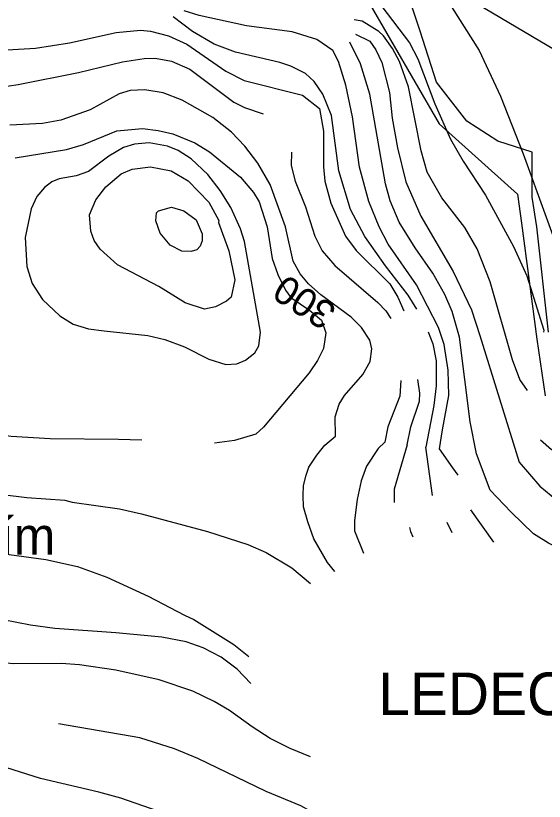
# Model space of a CAD drawing. Extents: x -662620 to -656370, y -1067090 to -1062990.
# Drawn here: x -660920.3 to -660671.9, y -1065837.4 to -1065468.5 of the extents above; entities that cross this region are included whole.
import ezdxf

# ---------------------------------------------------------------- set-up
doc = ezdxf.new("R2010")
doc.units = 0
for name, color, linetype in [('CHRANENE_LOZISKOVE_UZEMI', 7, 'Continuous'), ('HRANICE_KATASTRÁLNÍHO_ÚZEMÍ', 7, 'Continuous'), ('MÍSTNÍ_NÁZVY', 7, 'Continuous'), ('Ochr__pás__vod__zdroje_II__stupně', 7, 'Continuous'), ('POPIS_-_MZCHÚ', 7, 'Continuous'), ('VRSTEVNICE_ZDŮRAZNĚNÁ', 7, 'Continuous'), ('VRSTEVNICE_ZDŮRAZNĚNÁ_-_POPIS', 7, 'Continuous'), ('VRSTEVNICE_ZÁKLADNÍ', 7, 'Continuous')]:
    doc.layers.add(name, color=color, linetype=linetype)

msp = doc.modelspace()

# ---------------------------------------------------------------- linework, layer by layer
at = {"layer": 'CHRANENE_LOZISKOVE_UZEMI'}
msp.add_lwpolyline([(-661096.57, -1065944.42), (-661652.65, -1065558.91), (-661386.13, -1065362.86), (-661234.18, -1065237.85), (-660862.53, -1065376.49), (-660732.31, -1065445.66), (-660264.34, -1065722.38)], dxfattribs=at)
at = {"layer": 'HRANICE_KATASTRÁLNÍHO_ÚZEMÍ'}
msp.add_lwpolyline([(-660805.72, -1065089.02), (-660851.32, -1065259.88), (-660882.69, -1065372.12), (-660887.7, -1065375.53), (-660889.1, -1065376.51), (-660879.99, -1065382.24), (-660829.51, -1065412.73), (-660787.97, -1065437.5), (-660755.58, -1065459.98), (-660721.29, -1065519.33), (-660684.51, -1065552.34), (-660682.61, -1065565.91), (-660675.51, -1065620.4), (-660671.56, -1065647.03)], dxfattribs=at)
at = {"layer": 'Ochr__pás__vod__zdroje_II__stupně'}
msp.add_lwpolyline([(-660669.94, -1065617.13), (-660675.36, -1065567.65), (-660677.67, -1065553.71), (-660677.67, -1065532.65), (-660693.79, -1065527.44), (-660708.36, -1065518.08), (-660722.65, -1065499.69), (-660730.21, -1065475.73), (-660739.83, -1065447.13), (-660741.91, -1065434.08), (-660766.44, -1065423.12), (-660838.55, -1065385.6), (-660854.29, -1065377.16), (-660865.22, -1065371.3), (-660835.25, -1065270.78), (-660823.63, -1065223), (-660796.13, -1065127.73)], dxfattribs=at)
at = {"layer": 'VRSTEVNICE_ZDŮRAZNĚNÁ'}
for points in [[(-660870.75, -1065334.31), (-660842.73, -1065350.46), (-660822.72, -1065364.32), (-660778.7, -1065397.91), (-660748.54, -1065423.78), (-660735.1, -1065437.08), (-660721.52, -1065454.8), (-660702.51, -1065484.82), (-660692.51, -1065506.26), (-660681.93, -1065533.41), (-660660.21, -1065592.87), (-660641.91, -1065638.61), (-660634.76, -1065652.33), (-660626.19, -1065666.06), (-660609.48, -1065685.51)], [(-660721.19, -1065671.85), (-660719.77, -1065662.91), (-660716.81, -1065646.9), (-660717.09, -1065634.9), (-660718.95, -1065622.89), (-660721.67, -1065614.89), (-660731.96, -1065594.87), (-660745.25, -1065575.86), (-660749.54, -1065567.72), (-660754.4, -1065555.71), (-660758.69, -1065539.7), (-660761.97, -1065515.98), (-660765.12, -1065501.11), (-660768.55, -1065489.96), (-660771.27, -1065484.82), (-660778.84, -1065479.67), (-660790.42, -1065476.1), (-660811.86, -1065473.24), (-660834.16, -1065468.38), (-660841.16, -1065466.24)], [(-660920.49, -1065535.27), (-660896.47, -1065531.27), (-660888.47, -1065528.98), (-660872.75, -1065522.55), (-660860.74, -1065521.55), (-660853.31, -1065522.41), (-660846.45, -1065523.98), (-660836.16, -1065528.13), (-660829.3, -1065532.41), (-660814.72, -1065544.28), (-660808.57, -1065551.57), (-660805.85, -1065555.85), (-660802.14, -1065567.72), (-660799.71, -1065582.58), (-660797.14, -1065590.02), (-660793.56, -1065597.45), (-660790.99, -1065600.88), (-660782.27, -1065606.74), (-660776.55, -1065611.46), (-660774.55, -1065617.46), (-660775.7, -1065624.75), (-660778.55, -1065630.47), (-660782.41, -1065636.18), (-660803.84, -1065661.74)], [(-660860.95, -1065667.88), (-660872.02, -1065667.5), (-660904.12, -1065667.21), (-660922.47, -1065666.06), (-660936.22, -1065664.2), (-660949.98, -1065660.19), (-660960.01, -1065654.88), (-660967.9, -1065645.85), (-660969.94, -1065642.79)], [(-660803.84, -1065661.74), (-660807.52, -1065664.94), (-660817.56, -1065667.93), (-660826.89, -1065669.22)], [(-660712.36, -1065684.26), (-660714.95, -1065680.77), (-660721.19, -1065671.85)], [(-660706.64, -1065700.49), (-660695.74, -1065715.65)], [(-660699.05, -1065892.35), (-660707.4, -1065893.51), (-660716.66, -1065893.36), (-660724.11, -1065889.92), (-660730.56, -1065885.77), (-660736.15, -1065881.04), (-660750.91, -1065865.7), (-660766.82, -1065851.23), (-660772.7, -1065847.07), (-660786.32, -1065839.48), (-660802.65, -1065832.74), (-660834.76, -1065817.26), (-660845.65, -1065812.67), (-660861.99, -1065807.52), (-660900.11, -1065800.92)]]:
    msp.add_lwpolyline(points, dxfattribs=at)
at = {"layer": 'VRSTEVNICE_ZÁKLADNÍ'}
for points in [[(-660748.25, -1065464.23), (-660735.25, -1065481.24), (-660731.39, -1065488.82), (-660723.38, -1065509.83), (-660715.95, -1065526.55), (-660710.09, -1065536.84), (-660699.51, -1065552.85), (-660686.36, -1065576.87), (-660680.07, -1065590.59), (-660672.07, -1065616.17), (-660672.36, -1065617.03)], [(-660748.25, -1065464.23), (-660735.25, -1065481.24), (-660731.39, -1065488.82), (-660723.38, -1065509.83), (-660715.95, -1065526.55), (-660710.09, -1065536.84), (-660699.51, -1065552.85), (-660686.36, -1065576.87), (-660680.07, -1065590.59), (-660672.07, -1065616.17), (-660672.36, -1065617.03)], [(-660731.82, -1065606.28), (-660735.82, -1065599.73), (-660746.54, -1065586.01), (-660756.26, -1065572.15), (-660762.97, -1065559.43), (-660768.41, -1065541.42), (-660771.98, -1065515.4), (-660775.98, -1065505.4), (-660780.13, -1065499.4), (-660784.13, -1065495.68), (-660790.99, -1065492.25), (-660796.13, -1065490.53), (-660817, -1065485.67), (-660827.01, -1065481.81), (-660837.16, -1065475.95), (-660846.31, -1065469.09)], [(-660731.82, -1065606.28), (-660735.82, -1065599.73), (-660746.54, -1065586.01), (-660756.26, -1065572.15), (-660762.97, -1065559.43), (-660768.41, -1065541.42), (-660771.98, -1065515.4), (-660775.98, -1065505.4), (-660780.13, -1065499.4), (-660784.13, -1065495.68), (-660790.99, -1065492.25), (-660796.13, -1065490.53), (-660817, -1065485.67), (-660827.01, -1065481.81), (-660837.16, -1065475.95), (-660846.31, -1065469.09)], [(-660679.88, -1065644.47), (-660683.36, -1065639.33), (-660686.79, -1065630.04), (-660697.37, -1065593.45), (-660703.51, -1065578.01), (-660709.23, -1065568), (-660720.09, -1065554), (-660726.96, -1065541.99), (-660729.81, -1065531.98), (-660735.67, -1065501.97), (-660739.96, -1065489.96), (-660743.25, -1065483.96), (-660747.54, -1065477.96), (-660749.68, -1065475.95), (-660757.54, -1065471.09), (-660761.24, -1065470.46)], [(-660679.88, -1065644.47), (-660683.36, -1065639.33), (-660686.79, -1065630.04), (-660697.37, -1065593.45), (-660703.51, -1065578.01), (-660709.23, -1065568), (-660720.09, -1065554), (-660726.96, -1065541.99), (-660729.81, -1065531.98), (-660735.67, -1065501.97), (-660739.96, -1065489.96), (-660743.25, -1065483.96), (-660747.54, -1065477.96), (-660749.68, -1065475.95), (-660757.54, -1065471.09), (-660761.24, -1065470.46)], [(-660935.07, -1065485.1), (-660911.05, -1065483.82), (-660895.04, -1065481.24), (-660873.03, -1065476.38), (-660861.6, -1065475.38), (-660857.03, -1065475.81), (-660848.45, -1065477.96), (-660839.87, -1065481.81), (-660821.58, -1065494.54), (-660813, -1065498.97), (-660785.61, -1065505.79), (-660777.49, -1065512.1), (-660775.71, -1065522.69), (-660775.7, -1065539.42), (-660774.98, -1065546.28), (-660772.27, -1065556.57), (-660765.26, -1065572.01), (-660760.26, -1065578.72), (-660744.54, -1065594.45), (-660740.68, -1065600.59), (-660737.96, -1065607.02)], [(-660935.07, -1065485.1), (-660911.05, -1065483.82), (-660895.04, -1065481.24), (-660873.03, -1065476.38), (-660861.6, -1065475.38), (-660857.03, -1065475.81), (-660848.45, -1065477.96), (-660839.87, -1065481.81), (-660821.58, -1065494.54), (-660813, -1065498.97), (-660785.61, -1065505.79), (-660777.49, -1065512.1), (-660775.71, -1065522.69), (-660775.7, -1065539.42), (-660774.98, -1065546.28), (-660772.27, -1065556.57), (-660765.26, -1065572.01), (-660760.26, -1065578.72), (-660744.54, -1065594.45), (-660740.68, -1065600.59), (-660737.96, -1065607.02)], [(-660760.64, -1065477.14), (-660753.97, -1065480.53), (-660751.11, -1065484.53), (-660748.25, -1065490.53), (-660744.68, -1065504.54), (-660743.39, -1065516.55), (-660740.96, -1065530.56), (-660736.96, -1065546.56), (-660729.96, -1065562.57), (-660714.81, -1065588.59), (-660706.09, -1065606.6), (-660702.23, -1065618.6), (-660683.71, -1065678.06)], [(-660760.64, -1065477.14), (-660753.97, -1065480.53), (-660751.11, -1065484.53), (-660748.25, -1065490.53), (-660744.68, -1065504.54), (-660743.39, -1065516.55), (-660740.96, -1065530.56), (-660736.96, -1065546.56), (-660729.96, -1065562.57), (-660714.81, -1065588.59), (-660706.09, -1065606.6), (-660702.23, -1065618.6), (-660683.71, -1065678.06)], [(-660697.32, -1065691.29), (-660703.78, -1065674.17), (-660706.72, -1065659.27), (-660711.81, -1065619.46), (-660715.24, -1065607.45), (-660718.67, -1065599.45), (-660724.24, -1065589.44), (-660732.67, -1065577.44), (-660740.11, -1065565.43), (-660744.39, -1065555.43), (-660746.54, -1065547.42), (-660753.83, -1065505.4), (-660758.26, -1065491.11), (-660763.26, -1065480.96)], [(-660697.32, -1065691.29), (-660703.78, -1065674.17), (-660706.72, -1065659.27), (-660711.81, -1065619.46), (-660715.24, -1065607.45), (-660718.67, -1065599.45), (-660724.24, -1065589.44), (-660732.67, -1065577.44), (-660740.11, -1065565.43), (-660744.39, -1065555.43), (-660746.54, -1065547.42), (-660753.83, -1065505.4), (-660758.26, -1065491.11), (-660763.26, -1065480.96)], [(-661000.38, -1065496.64), (-660996.62, -1065498.87), (-660990.24, -1065500.82), (-660976.23, -1065503.25), (-660962.22, -1065504.4), (-660947.36, -1065503.97), (-660931.92, -1065502.68), (-660919.06, -1065500.83), (-660890.76, -1065495.25), (-660870.17, -1065490.25), (-660859.88, -1065488.68), (-660854.74, -1065488.53), (-660847.02, -1065489.82), (-660838.44, -1065493.68), (-660817.86, -1065509.12), (-660812.72, -1065511.69), (-660804, -1065514.55)], [(-661000.38, -1065496.64), (-660996.62, -1065498.87), (-660990.24, -1065500.82), (-660976.23, -1065503.25), (-660962.22, -1065504.4), (-660947.36, -1065503.97), (-660931.92, -1065502.68), (-660919.06, -1065500.83), (-660890.76, -1065495.25), (-660870.17, -1065490.25), (-660859.88, -1065488.68), (-660854.74, -1065488.53), (-660847.02, -1065489.82), (-660838.44, -1065493.68), (-660817.86, -1065509.12), (-660812.72, -1065511.69), (-660804, -1065514.55)], [(-660770.08, -1065665.87), (-660770.12, -1065656.91), (-660768.26, -1065650.9), (-660765.83, -1065646.9), (-660757.11, -1065636.9), (-660753.68, -1065630.89), (-660752.97, -1065624.89), (-660753.83, -1065620.89), (-660757.83, -1065614.89), (-660762.69, -1065610.03), (-660776.98, -1065599.59), (-660782.7, -1065594.45), (-660786.7, -1065589.73), (-660789.99, -1065583.73), (-660793.56, -1065567.72), (-660800.71, -1065547.71), (-660806.57, -1065537.7), (-660812.57, -1065529.7), (-660818.86, -1065523.27), (-660827.72, -1065516.26), (-660842.02, -1065508.11), (-660851.02, -1065504.68), (-660859.6, -1065503.25), (-660866.46, -1065503.68), (-660871.6, -1065505.26), (-660885.33, -1065512.69), (-660899.05, -1065517.55), (-660907.62, -1065519.12), (-660923.06, -1065519.84)], [(-660770.08, -1065665.87), (-660770.12, -1065656.91), (-660768.26, -1065650.9), (-660765.83, -1065646.9), (-660757.11, -1065636.9), (-660753.68, -1065630.89), (-660752.97, -1065624.89), (-660753.83, -1065620.89), (-660757.83, -1065614.89), (-660762.69, -1065610.03), (-660776.98, -1065599.59), (-660782.7, -1065594.45), (-660786.7, -1065589.73), (-660789.99, -1065583.73), (-660793.56, -1065567.72), (-660800.71, -1065547.71), (-660806.57, -1065537.7), (-660812.57, -1065529.7), (-660818.86, -1065523.27), (-660827.72, -1065516.26), (-660842.02, -1065508.11), (-660851.02, -1065504.68), (-660859.6, -1065503.25), (-660866.46, -1065503.68), (-660871.6, -1065505.26), (-660885.33, -1065512.69), (-660899.05, -1065517.55), (-660907.62, -1065519.12), (-660923.06, -1065519.84)], [(-660886.06, -1065541.7), (-660891.81, -1065543.75), (-660899.9, -1065545.13), (-660903.34, -1065546.56), (-660906.77, -1065549.14), (-660910.34, -1065553.42), (-660913.05, -1065559.14), (-660915.91, -1065572.58), (-660915.06, -1065586.3), (-660912.48, -1065594.3), (-660907.77, -1065601.74), (-660899.48, -1065609.45), (-660893.22, -1065613.41), (-660886.08, -1065615.46), (-660878.75, -1065616.46), (-660858.17, -1065618.74), (-660850.16, -1065620.6), (-660841.02, -1065624.03), (-660829.58, -1065629.75), (-660821.58, -1065632.32), (-660816.43, -1065631.89), (-660812.29, -1065630.32), (-660807.86, -1065626.75), (-660806, -1065623.46), (-660805.28, -1065617.17), (-660812.86, -1065574.58), (-660814.72, -1065568.58), (-660819.15, -1065558.57), (-660824.15, -1065550.57), (-660830.01, -1065543.13), (-660837.87, -1065535.7), (-660843.88, -1065531.84), (-660849.02, -1065529.84), (-660857.6, -1065528.27), (-660864.46, -1065528.84), (-660869.6, -1065530.41), (-660876.46, -1065534.41), (-660886.06, -1065541.7)], [(-660886.06, -1065541.7), (-660891.81, -1065543.75), (-660899.9, -1065545.13), (-660903.34, -1065546.56), (-660906.77, -1065549.14), (-660910.34, -1065553.42), (-660913.05, -1065559.14), (-660915.91, -1065572.58), (-660915.06, -1065586.3), (-660912.48, -1065594.3), (-660907.77, -1065601.74), (-660899.48, -1065609.45), (-660893.22, -1065613.41), (-660886.08, -1065615.46), (-660878.75, -1065616.46), (-660858.17, -1065618.74), (-660850.16, -1065620.6), (-660841.02, -1065624.03), (-660829.58, -1065629.75), (-660821.58, -1065632.32), (-660816.43, -1065631.89), (-660812.29, -1065630.32), (-660807.86, -1065626.75), (-660806, -1065623.46), (-660805.28, -1065617.17), (-660812.86, -1065574.58), (-660814.72, -1065568.58), (-660819.15, -1065558.57), (-660824.15, -1065550.57), (-660830.01, -1065543.13), (-660837.87, -1065535.7), (-660843.88, -1065531.84), (-660849.02, -1065529.84), (-660857.6, -1065528.27), (-660864.46, -1065528.84), (-660869.6, -1065530.41), (-660876.46, -1065534.41), (-660886.06, -1065541.7)], [(-660790.73, -1065532.57), (-660790.92, -1065538.89), (-660788.99, -1065546.28), (-660784.13, -1065558.28), (-660779.7, -1065572.01), (-660776.27, -1065578.87), (-660770.41, -1065585.87), (-660750.11, -1065603.16), (-660746.39, -1065607.02), (-660743.97, -1065610.74)], [(-660790.73, -1065532.57), (-660790.92, -1065538.89), (-660788.99, -1065546.28), (-660784.13, -1065558.28), (-660779.7, -1065572.01), (-660776.27, -1065578.87), (-660770.41, -1065585.87), (-660750.11, -1065603.16), (-660746.39, -1065607.02), (-660743.97, -1065610.74)], [(-660829.58, -1065555.99), (-660824.82, -1065564.72), (-660825.01, -1065565.57), (-660820.15, -1065578.87), (-660817.29, -1065592.59), (-660819, -1065600.59), (-660821.29, -1065602.59), (-660826.44, -1065605.19), (-660831.59, -1065606.31), (-660840.73, -1065603.31), (-660853.02, -1065595.73), (-660872.46, -1065585.44), (-660880.61, -1065578.15), (-660883.47, -1065574.01), (-660885.04, -1065569.72), (-660885.67, -1065561.96), (-660882.61, -1065555), (-660877.89, -1065548.85), (-660870.75, -1065542.7), (-660865.6, -1065540.56), (-660857.03, -1065539.42), (-660847.31, -1065541.42), (-660839.3, -1065545.99), (-660829.58, -1065555.99)], [(-660829.58, -1065555.99), (-660824.82, -1065564.72), (-660825.01, -1065565.57), (-660820.15, -1065578.87), (-660817.29, -1065592.59), (-660819, -1065600.59), (-660821.29, -1065602.59), (-660826.44, -1065605.19), (-660831.59, -1065606.31), (-660840.73, -1065603.31), (-660853.02, -1065595.73), (-660872.46, -1065585.44), (-660880.61, -1065578.15), (-660883.47, -1065574.01), (-660885.04, -1065569.72), (-660885.67, -1065561.96), (-660882.61, -1065555), (-660877.89, -1065548.85), (-660870.75, -1065542.7), (-660865.6, -1065540.56), (-660857.03, -1065539.42), (-660847.31, -1065541.42), (-660839.3, -1065545.99), (-660829.58, -1065555.99)], [(-660841.26, -1065560.07), (-660835.44, -1065564.29), (-660832.73, -1065570.86), (-660832.73, -1065574.29), (-660833.58, -1065576.72), (-660835.16, -1065578.44), (-660837.87, -1065579.15), (-660842.16, -1065579.01), (-660847.73, -1065576.29), (-660852.45, -1065570.58), (-660854.45, -1065564.86), (-660854.17, -1065561.14), (-660853.17, -1065560.14), (-660847.02, -1065558.43), (-660841.26, -1065560.07)], [(-660841.26, -1065560.07), (-660835.44, -1065564.29), (-660832.73, -1065570.86), (-660832.73, -1065574.29), (-660833.58, -1065576.72), (-660835.16, -1065578.44), (-660837.87, -1065579.15), (-660842.16, -1065579.01), (-660847.73, -1065576.29), (-660852.45, -1065570.58), (-660854.45, -1065564.86), (-660854.17, -1065561.14), (-660853.17, -1065560.14), (-660847.02, -1065558.43), (-660841.26, -1065560.07)], [(-660726.53, -1065616.87), (-660724.36, -1065622.63), (-660722.77, -1065630.62), (-660722.67, -1065642.33), (-660723.81, -1065651.48), (-660727.57, -1065671.07)], [(-660726.53, -1065616.87), (-660724.36, -1065622.63), (-660722.77, -1065630.62), (-660722.67, -1065642.33), (-660723.81, -1065651.48), (-660727.57, -1065671.07)], [(-661051.12, -1065631.49), (-661045.86, -1065636.4), (-661025.94, -1065651.87), (-661017.91, -1065659.47), (-661008.74, -1065670.79), (-661006.74, -1065674.23), (-661003.73, -1065677.67), (-660999, -1065684.55), (-660993.55, -1065690.43), (-660989.54, -1065693.87), (-660975.35, -1065702.61), (-660959.3, -1065710.92), (-660956.43, -1065712.21), (-660947.26, -1065715.51), (-660926.77, -1065720.95), (-660906.13, -1065723.82), (-660891.22, -1065727.12), (-660877.46, -1065732.13), (-660857.97, -1065741.02), (-660841, -1065750.03), (-660836.62, -1065752.05), (-660817.84, -1065763.8), (-660810.82, -1065769.39)], [(-661051.12, -1065631.49), (-661045.86, -1065636.4), (-661025.94, -1065651.87), (-661017.91, -1065659.47), (-661008.74, -1065670.79), (-661006.74, -1065674.23), (-661003.73, -1065677.67), (-660999, -1065684.55), (-660993.55, -1065690.43), (-660989.54, -1065693.87), (-660975.35, -1065702.61), (-660959.3, -1065710.92), (-660956.43, -1065712.21), (-660947.26, -1065715.51), (-660926.77, -1065720.95), (-660906.13, -1065723.82), (-660891.22, -1065727.12), (-660877.46, -1065732.13), (-660857.97, -1065741.02), (-660841, -1065750.03), (-660836.62, -1065752.05), (-660817.84, -1065763.8), (-660810.82, -1065769.39)], [(-660994.21, -1065638.45), (-660989.54, -1065647.86), (-660986.38, -1065653.02), (-660978.22, -1065663.91), (-660971.77, -1065670.93), (-660963.31, -1065677.81), (-660954, -1065683.69), (-660943.39, -1065688.71), (-660936.8, -1065691), (-660926.48, -1065693.29), (-660915.01, -1065694.73), (-660897.24, -1065696.02), (-660893.8, -1065696.88), (-660871.45, -1065700.03), (-660861.13, -1065702.32), (-660830.17, -1065710.63), (-660811.25, -1065716.8), (-660802.65, -1065720.52), (-660790.61, -1065727.69), (-660781.73, -1065735.14)], [(-660994.21, -1065638.45), (-660989.54, -1065647.86), (-660986.38, -1065653.02), (-660978.22, -1065663.91), (-660971.77, -1065670.93), (-660963.31, -1065677.81), (-660954, -1065683.69), (-660943.39, -1065688.71), (-660936.8, -1065691), (-660926.48, -1065693.29), (-660915.01, -1065694.73), (-660897.24, -1065696.02), (-660893.8, -1065696.88), (-660871.45, -1065700.03), (-660861.13, -1065702.32), (-660830.17, -1065710.63), (-660811.25, -1065716.8), (-660802.65, -1065720.52), (-660790.61, -1065727.69), (-660781.73, -1065735.14)], [(-660739.33, -1065639.86), (-660739.82, -1065647.19), (-660745.39, -1065661.48), (-660746.89, -1065668.7)], [(-660739.33, -1065639.86), (-660739.82, -1065647.19), (-660745.39, -1065661.48), (-660746.89, -1065668.7)], [(-660736.33, -1065670), (-660734.67, -1065661.62), (-660730.61, -1065649.53), (-660730.42, -1065645.81), (-660731.41, -1065639.31)], [(-660736.33, -1065670), (-660734.67, -1065661.62), (-660730.61, -1065649.53), (-660730.42, -1065645.81), (-660731.41, -1065639.31)], [(-660770.33, -1065729.47), (-660773.85, -1065725.25), (-660780.15, -1065714.07), (-660783.09, -1065706.09), (-660785.13, -1065699.08), (-660785.17, -1065693.72), (-660785.09, -1065689.11), (-660783.88, -1065684.26), (-660782.59, -1065680.54), (-660778.86, -1065674.8), (-660774.99, -1065670.22), (-660770.08, -1065665.87)], [(-660770.33, -1065729.47), (-660773.85, -1065725.25), (-660780.15, -1065714.07), (-660783.09, -1065706.09), (-660785.13, -1065699.08), (-660785.17, -1065693.72), (-660785.09, -1065689.11), (-660783.88, -1065684.26), (-660782.59, -1065680.54), (-660778.86, -1065674.8), (-660774.99, -1065670.22), (-660770.08, -1065665.87)], [(-660746.89, -1065668.7), (-660750, -1065671.79), (-660755.5, -1065679.96), (-660757.94, -1065686.84), (-660759.8, -1065695.73), (-660761.17, -1065705.56), (-660761.08, -1065710.44), (-660756.93, -1065720.81)], [(-660746.89, -1065668.7), (-660750, -1065671.79), (-660755.5, -1065679.96), (-660757.94, -1065686.84), (-660759.8, -1065695.73), (-660761.17, -1065705.56), (-660761.08, -1065710.44), (-660756.93, -1065720.81)], [(-660673.74, -1065667.7), (-660668.59, -1065672.16), (-660645.93, -1065682.47)], [(-660673.74, -1065667.7), (-660668.59, -1065672.16), (-660645.93, -1065682.47)], [(-660736.33, -1065670), (-660742.46, -1065690.86), (-660742.46, -1065697.02)], [(-660736.33, -1065670), (-660742.46, -1065690.86), (-660742.46, -1065697.02)], [(-660724.53, -1065693.75), (-660727.57, -1065671.07)], [(-660724.53, -1065693.75), (-660727.57, -1065671.07)], [(-660683.71, -1065678.06), (-660673.95, -1065689.42), (-660663.35, -1065698.17), (-660659.48, -1065700.74), (-660641.42, -1065715.36), (-660636.26, -1065721.81), (-660626.95, -1065735.71), (-660623.08, -1065743.02), (-660610.61, -1065758.93), (-660604.01, -1065772.55), (-660602.15, -1065778.85), (-660599.57, -1065785.16), (-660598, -1065791.89)], [(-660683.71, -1065678.06), (-660673.95, -1065689.42), (-660663.35, -1065698.17), (-660659.48, -1065700.74), (-660641.42, -1065715.36), (-660636.26, -1065721.81), (-660626.95, -1065735.71), (-660623.08, -1065743.02), (-660610.61, -1065758.93), (-660604.01, -1065772.55), (-660602.15, -1065778.85), (-660599.57, -1065785.16), (-660598, -1065791.89)], [(-660627.61, -1065748.07), (-660639.56, -1065737.43), (-660647.15, -1065729.7), (-660652.6, -1065726.54), (-660659.19, -1065721.67), (-660669.94, -1065716.22), (-660676.96, -1065711.78), (-660687.57, -1065701.6), (-660697.32, -1065691.29)], [(-660627.61, -1065748.07), (-660639.56, -1065737.43), (-660647.15, -1065729.7), (-660652.6, -1065726.54), (-660659.19, -1065721.67), (-660669.94, -1065716.22), (-660676.96, -1065711.78), (-660687.57, -1065701.6), (-660697.32, -1065691.29)], [(-660781.79, -1065816.45), (-660791.33, -1065812.53), (-660800.65, -1065807.8), (-660809.25, -1065802.36), (-660819.85, -1065794.76), (-660827.02, -1065790.46), (-660837.05, -1065785.59), (-660852.81, -1065780.29), (-660873.17, -1065775.84), (-660890.36, -1065773.26), (-660898.96, -1065772.69), (-660921.32, -1065772.83), (-660938.52, -1065771.11), (-660954, -1065767.96), (-660964.31, -1065764.09), (-660981.51, -1065756.21), (-660998.14, -1065746.61), (-661018.77, -1065733.42), (-661027.23, -1065727.26), (-661040.85, -1065719.23), (-661042.28, -1065717.94), (-661073.81, -1065702.61), (-661080.97, -1065699.6), (-661093.66, -1065693.84)], [(-660781.79, -1065816.45), (-660791.33, -1065812.53), (-660800.65, -1065807.8), (-660809.25, -1065802.36), (-660819.85, -1065794.76), (-660827.02, -1065790.46), (-660837.05, -1065785.59), (-660852.81, -1065780.29), (-660873.17, -1065775.84), (-660890.36, -1065773.26), (-660898.96, -1065772.69), (-660921.32, -1065772.83), (-660938.52, -1065771.11), (-660954, -1065767.96), (-660964.31, -1065764.09), (-660981.51, -1065756.21), (-660998.14, -1065746.61), (-661018.77, -1065733.42), (-661027.23, -1065727.26), (-661040.85, -1065719.23), (-661042.28, -1065717.94), (-661073.81, -1065702.61), (-661080.97, -1065699.6), (-661093.66, -1065693.84)], [(-660715.29, -1065711.39), (-660717.61, -1065706.44)], [(-660715.29, -1065711.39), (-660717.61, -1065706.44)], [(-660735.31, -1065708.74), (-660734.85, -1065710.75), (-660733.72, -1065713.21)], [(-660735.31, -1065708.74), (-660734.85, -1065710.75), (-660733.72, -1065713.21)], [(-660809.88, -1065782.02), (-660816.27, -1065775.27), (-660823.72, -1065769.68), (-660832.18, -1065765.38), (-660840.2, -1065762.51), (-660851.67, -1065760.36), (-660873.17, -1065758.21), (-660901.83, -1065756.21), (-660913.29, -1065754.63), (-660926.19, -1065752.2), (-660939.09, -1065748.04), (-660950.56, -1065743.17), (-660961.16, -1065737.43), (-660973.06, -1065728.98)], [(-660809.88, -1065782.02), (-660816.27, -1065775.27), (-660823.72, -1065769.68), (-660832.18, -1065765.38), (-660840.2, -1065762.51), (-660851.67, -1065760.36), (-660873.17, -1065758.21), (-660901.83, -1065756.21), (-660913.29, -1065754.63), (-660926.19, -1065752.2), (-660939.09, -1065748.04), (-660950.56, -1065743.17), (-660961.16, -1065737.43), (-660973.06, -1065728.98)], [(-660687.16, -1065902.58), (-660697.13, -1065904.98), (-660709.78, -1065906.83), (-660721.82, -1065906.69), (-660731.85, -1065905.26), (-660737.87, -1065903.25), (-660745.9, -1065899.38), (-660756.51, -1065892.07), (-660769.4, -1065880.89), (-660784.02, -1065870.43), (-660794.63, -1065865.27), (-660814.69, -1065858.25), (-660853.39, -1065842.05), (-660870.87, -1065835.89), (-660881.19, -1065833.03), (-660908.71, -1065826.58), (-660950.27, -1065813.54), (-661003.58, -1065792.75), (-661020.78, -1065785.3), (-661060.91, -1065766.53), (-661085.27, -1065757.5), (-661091.87, -1065755.92), (-661100.91, -1065754.74)], [(-660687.16, -1065902.58), (-660697.13, -1065904.98), (-660709.78, -1065906.83), (-660721.82, -1065906.69), (-660731.85, -1065905.26), (-660737.87, -1065903.25), (-660745.9, -1065899.38), (-660756.51, -1065892.07), (-660769.4, -1065880.89), (-660784.02, -1065870.43), (-660794.63, -1065865.27), (-660814.69, -1065858.25), (-660853.39, -1065842.05), (-660870.87, -1065835.89), (-660881.19, -1065833.03), (-660908.71, -1065826.58), (-660950.27, -1065813.54), (-661003.58, -1065792.75), (-661020.78, -1065785.3), (-661060.91, -1065766.53), (-661085.27, -1065757.5), (-661091.87, -1065755.92), (-661100.91, -1065754.74)]]:
    msp.add_lwpolyline(points, dxfattribs=at)

# ---------------------------------------------------------------- texts
at = {"layer": 'MÍSTNÍ_NÁZVY'}
msp.add_text('K Cholticím', height=17.5, dxfattribs=at).set_placement((-661021.32, -1065721.53))
at = {"layer": 'POPIS_-_MZCHÚ'}
msp.add_text('LEDEC', height=20, dxfattribs=at).set_placement((-660749.93, -1065796.89))
at = {"layer": 'VRSTEVNICE_ZDŮRAZNĚNÁ_-_POPIS'}
msp.add_text('300', height=13.2, rotation=147.158, dxfattribs=at).set_placement((-660768.73, -1065605.49))

doc.saveas('drawing.dxf')
